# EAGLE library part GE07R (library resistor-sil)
SIL RESISTOR
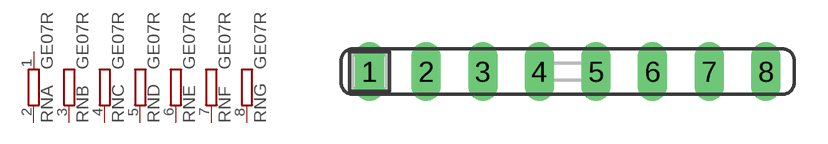
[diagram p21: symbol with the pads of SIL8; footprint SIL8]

Designator prefix RN; gates A=R-NV B=R-NV1 C=R-NV1 D=R-NV1 E=R-NV1 F=R-NV1 G=R-NV1

## GE07R (OC_FARNELL: unknown; OC_NEWARK: unknown)  [SIL8]
1  A:1  pas
2  A:2  pas
3  B:2  pas
4  C:2  pas
5  D:2  pas
6  E:2  pas
7  F:2  pas
8  G:2  pas

## Footprint SIL8 (pad centres in mm)
Single In Line
drill 0.813 long: 1 -8.89,0; 2 -6.35,0; 3 -3.81,0; 4 -1.27,0; 5 1.27,0; 6 3.81,0; 7 6.35,0; 8 8.89,0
